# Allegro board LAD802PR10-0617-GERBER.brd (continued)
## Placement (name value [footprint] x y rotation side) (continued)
PC677  1U_0402_10V6K  [C_0402]  155.42 94.92 0 bottom
PC678  680P_0603_50V7K  [C_0603]  144.86 91.65 270 top
PC679  1000P_0402_50V7K  [C_0402]  152.05 88.44 180 top
PC680  1000P_0402_50V7K  [C_0402]  159.24 76.1 180 top
PC681  1000P_0402_50V7K  [C_0402]  148.94 98.16 180 bottom
PC685  1U_0402_10V6K  [C_0402]  149.45 73.74 180 top
PC686  10P_0402_25V8J  [C_0402]  159.24 75.18 180 bottom
PC687  10P_0402_25V8J  [C_0402]  148.94 97.27 180 top
PC688  10P_0402_25V8J  [C_0402]  152.05 87.55 180 top
PC690  33U_25V_M  [C_25CL33LD]  160.8 93.85 270 bottom
PC691  1000P_0402_25V8J  [C_0402]  159.24 75.18 180 top
PC692  1000P_0402_25V8J  [C_0402]  148.92 96.4 180 top
PC693  1000P_0402_25V8J  [C_0402]  148.94 96.39 180 bottom
PC694  1000P_0402_25V8J  [C_0402]  159.24 74.29 180 top
PC695  10P_0402_25V8J  [C_0402]  164.49 51.57 90 bottom
PC705  2200P_0402_25V7K  [C_0402]  198.96 30.11 90 bottom
PC708  0.1U_0402_25V6  [C_0402]  194.38 40.16 0 bottom
PC711  0.01UF_0402_25V7K  [C_0402]  189.81 33.1 0 top
PC721  0.22U_0402_16V7K  [C_0402]  199.74 35.33 180 bottom
PC742  5600P_0402_25V7K  [C_0402]  89.95 123.08 180 bottom
PC744  0.1U_0402_25V6  [C_0402]  95.13 123.08 0 bottom
PC747  0.1U_0402_25V6  [C_0402]  193.58 32.15 180 bottom
PC748  0.1U_0402_25V7K  [C_0402]  188.94 37.93 180 bottom
PC749  2200P_0402_25V7K  [C_0402]  188.03 39.33 0 bottom
PC750  0.22U_0603_25V7K  [C_0603]  194.71 30.69 90 bottom
PC751  560P_0402_50V7K  [C_0402]  190.44 41.39 270 bottom
PC752  0.015U_0402_25V7K  [C_0402]  190.43 42.31 0 bottom
PC753  10P_0402_50V8J  [C_0402]  192.6 41.93 0 bottom
PC757  1U_0603_25V6  [C_0603]  199.55 38.93 180 bottom
PC760  10U_0805_25V6K  [C_0805]  200.25 30.02 90 bottom
PC761  10U_0805_25V6K  [C_0805]  215.58 23.84 0 bottom
PC762  10U_0805_25V6K  [C_0805]  200.25 30.02 90 top
PC763  10U_0805_25V6K  [C_0805]  201.96 30.02 90 top
PC764  10U_0805_25V6K  [C_0805]  201.96 30.02 90 bottom
PC765  0.1U_0402_25V7K  [C_0402]  198.08 30.11 90 bottom
PC766  10U_0805_25V6K  [C_0805]  215.59 22.12 0 bottom
PC767  680P_0603_50V7K  [C_0603]  210.48 33.62 270 top
PC768  1U_0402_16V6K  [C_0402]  199.93 37.87 180 bottom
PC769  1U_0402_16V6K  [C_0402]  199.93 36.98 180 bottom
PC775  10U_0805_25V6K  [C_0805]  214.14 21.77 270 bottom
PC776  10U_0805_25V6K  [C_0805]  215.58 22.12 0 top
PC777  0.1U_0402_25V7K  [C_0402]  215.72 25.17 0 bottom
PC778  10U_0805_25V6K  [C_0805]  215.58 23.83 0 top
PC779  0.1U_0402_25V7K  [C_0402]  210.01 25.69 270 top
PC780  1000P_0402_25V8J  [C_0402]  198.96 30.11 90 top
PC781  1000P_0402_25V8J  [C_0402]  198.08 30.11 90 top
PC790  0.01U_0402_16V7K  [C_0402]  186.26 37.25 270 top
PC801  1U_0402_6.3V6K  [C_0402]  52.43 3.91 0 bottom
PC802  10U_0805_10V6K  [C_0805]  54.73 6.05 270 bottom
PC803  0.01U_0402_25V7K  [C_0402]  44.64 7.44 90 bottom
PC804  10U_0805_10V6K  [C_0805]  45.22 6.24 270 bottom
PC805  0.1U_0402_10V6K  [C_0402]  54.31 9.32 0 bottom
PC1001  22U_0603_6.3V6M  [C_0603]  116.56 51.72 90 top
PC1002  22U_0603_6.3V6M  [C_0603]  134.85 69.58 0 bottom
PC1003  22U_0603_6.3V6M  [C_0603]  143.53 75.14 270 bottom
PC1004  22U_0603_6.3V6M  [C_0603]  134.86 68.05 0 top
PC1005  22U_0603_6.3V6M  [C_0603]  115.35 51.72 90 top
PC1006  22U_0603_6.3V6M  [C_0603]  144.93 75.14 270 bottom
PC1007  22U_0603_6.3V6M  [C_0603]  111.73 51.7 90 top
PC1008  22U_0603_6.3V6M  [C_0603]  114.14 51.72 90 top
PC1009  22U_0603_6.3V6M  [C_0603]  112.94 51.7 90 top
PC1010  22U_0603_6.3V6M  [C_0603]  116.56 55.5 270 top
PC1011  22U_0603_6.3V6M  [C_0603]  115.35 55.49 270 top
PC1012  22U_0603_6.3V6M  [C_0603]  134.86 65 0 top
PC1013  22U_0603_6.3V6M  [C_0603]  138.07 67.02 0 bottom
PC1014  22U_0603_6.3V6M  [C_0603]  115.34 91.01 270 bottom
PC1015  22U_0603_6.3V6M  [C_0603]  113.81 91.01 270 bottom
PC1016  22U_0603_6.3V6M  [C_0603]  112.29 87.72 270 bottom
PC1017  22U_0603_6.3V6M  [C_0603]  116.98 84.67 270 bottom
PC1018  22U_0603_6.3V6M  [C_0603]  110.78 87.78 270 bottom
PC1019  22U_0603_6.3V6M  [C_0603]  115.33 87.7 270 bottom
PC1020  22U_0603_6.3V6M  [C_0603]  116.93 87.73 270 bottom
PC1021  22U_0603_6.3V6M  [C_0603]  115.37 84.72 270 bottom
PC1022  22U_0603_6.3V6M  [C_0603]  113.85 84.7 270 bottom
PC1023  22U_0603_6.3V6M  [C_0603]  116.92 94 270 bottom
PC1024  22U_0603_6.3V6M  [C_0603]  113.69 94 270 bottom
PC1025  22U_0603_6.3V6M  [C_0603]  116.92 96.92 270 bottom
PC1026  22U_0603_6.3V6M  [C_0603]  112.03 96.98 270 bottom
PC1027  22U_0603_6.3V6M  [C_0603]  115.34 94 270 bottom
PC1028  22U_0603_6.3V6M  [C_0603]  114.64 66.3 270 top
PC1029  22U_0603_6.3V6M  [C_0603]  115.84 66.3 270 top
PC1030  1U_0201_6.3V6M  [C_0201]  108.02 53.63 270 top
PC1031  1U_0201_6.3V6M  [C_0201]  110.21 58.92 90 top
PC1032  1U_0201_6.3V6M  [C_0201]  110.8 53.18 90 top
PC1033  1U_0201_6.3V6M  [C_0201]  109.06 58.92 90 top
PC1034  1U_0201_6.3V6M  [C_0201]  109.67 55.41 270 top
PC1035  1U_0201_6.3V6M  [C_0201]  110.78 58.92 90 top
PC1036  1U_0201_6.3V6M  [C_0201]  109.67 53.18 90 top
PC1037  1U_0201_6.3V6M  [C_0201]  110.24 53.18 90 top
PC1038  1U_0201_6.3V6M  [C_0201]  108.1 54.38 90 top
PC1039  1U_0201_6.3V6M  [C_0201]  110.23 55.41 270 top
PC1040  1U_0201_6.3V6M  [C_0201]  111.15 66.46 270 top
PC1041  1U_0201_6.3V6M  [C_0201]  110 66.46 270 top
PC1042  1U_0201_6.3V6M  [C_0201]  108.31 63.18 0 top
PC1043  1U_0201_6.3V6M  [C_0201]  110.64 61.23 270 top
PC1044  1U_0201_6.3V6M  [C_0201]  111.27 61.23 270 top
PC1045  1U_0201_6.3V6M  [C_0201]  109.37 61.23 270 top
PC1046  1U_0201_6.3V6M  [C_0201]  110.03 65.28 0 top
PC1047  1U_0201_6.3V6M  [C_0201]  110 61.23 270 top
PC1048  1U_0201_6.3V6M  [C_0201]  117.34 59.37 180 top
PC1049  1U_0201_6.3V6M  [C_0201]  108.73 61.23 270 top
PC1050  1U_0201_6.3V6M  [C_0201]  110.8 55.4 270 top
PC1051  1U_0201_6.3V6M  [C_0201]  111.46 59.26 0 top
PC1052  1U_0201_6.3V6M  [C_0201]  111.46 58.69 0 top
PC1053  1U_0201_6.3V6M  [C_0201]  110.78 56.62 90 top
PC1054  1U_0201_6.3V6M  [C_0201]  110.22 56.62 90 top
PC1055  1U_0201_6.3V6M  [C_0201]  117.34 58.8 180 top
PC1056  1U_0201_6.3V6M  [C_0201]  110.03 64.71 0 top
PC1057  22U_0603_6.3V6M  [C_0603]  117.24 48.2 90 top
PC1058  22U_0603_6.3V6M  [C_0603]  151.92 56.15 270 top
PC1059  22U_0603_6.3V6M  [C_0603]  150.08 56.15 270 top
PC1060  22U_0603_6.3V6M  [C_0603]  148.43 56.15 270 top
PC1061  22U_0603_6.3V6M  [C_0603]  116.53 56.53 90 top
PC1062  330U_2V_M  [C_5X4P5]  136.61 80.77 270 bottom
PC1063  330U_2V_M  [C_5X4P5]  135.28 93.36 90 bottom
PC1064  22U_0603_6.3V6M  [C_0603]  115.32 56.52 90 top
PC1065  22U_0603_6.3V6M  [C_0603]  114.12 56.52 90 top
PC1066  22U_0603_6.3V6M  [C_0603]  112.91 56.52 90 top
PC1067  22U_0603_6.3V6M  [C_0603]  111.7 56.52 90 top
PC1068  22U_0603_6.3V6M  [C_0603]  134.85 68.05 0 bottom
PC1069  22U_0603_6.3V6M  [C_0603]  138.04 71.63 0 top
PC1070  22U_0603_6.3V6M  [C_0603]  136.42 75.14 270 bottom
PC1071  22U_0603_6.3V6M  [C_0603]  134.86 66.53 0 top
PC1072  22U_0603_6.3V6M  [C_0603]  138.07 67.02 0 top
PC1073  22U_0603_6.3V6M  [C_0603]  138.06 68.54 0 bottom
PC1074  22U_0603_6.3V6M  [C_0603]  140.61 75.14 270 bottom
PC1075  22U_0603_6.3V6M  [C_0603]  139.21 75.14 270 bottom
PC1076  22U_0603_6.3V6M  [C_0603]  134.85 66.53 0 bottom
PC1077  22U_0603_6.3V6M  [C_0603]  134.85 65 0 bottom
PC1078  22U_0603_6.3V6M  [C_0603]  138.07 70.06 0 top
PC1079  22U_0603_6.3V6M  [C_0603]  137.82 75.14 270 bottom
PC1080  22U_0603_6.3V6M  [C_0603]  138.07 70.07 0 bottom
PC1081  22U_0603_6.3V6M  [C_0603]  138.07 68.53 0 top
PC1082  22U_0603_6.3V6M  [C_0603]  135.02 75.14 270 bottom
PC1083  1U_0201_6.3V6M  [C_0201]  109.62 56.61 90 top
PC1084  1U_0201_6.3V6M  [C_0201]  109.05 56.61 90 top
PC1085  1U_0201_6.3V6M  [C_0201]  107.45 53.65 270 top
PC1086  1U_0201_6.3V6M  [C_0201]  110.26 52.11 270 top
PC1087  1U_0201_6.3V6M  [C_0201]  110.83 52.11 270 top
PC1088  1U_0201_6.3V6M  [C_0201]  109.63 58.92 90 top
PC1089  1U_0201_6.3V6M  [C_0201]  117.27 50.92 180 top
PC1090  1U_0201_6.3V6M  [C_0201]  117.27 50.36 180 top
PC1091  1U_0201_6.3V6M  [C_0201]  112.17 50.36 0 top
PC1092  1U_0201_6.3V6M  [C_0201]  114.42 50.93 180 top
PC1093  1U_0201_6.3V6M  [C_0201]  115.03 50.36 0 top
PC1094  1U_0201_6.3V6M  [C_0201]  115.03 50.93 0 top
PC1095  1U_0201_6.3V6M  [C_0201]  114.42 50.36 180 top
PC1096  1U_0201_6.3V6M  [C_0201]  112.17 50.93 0 top
PC1097  1U_0201_6.3V6M  [C_0201]  111.55 50.93 180 top
PC1098  1U_0201_6.3V6M  [C_0201]  111.56 50.36 180 top
PC1099  1U_0201_6.3V6M  [C_0201]  109.33 50.93 0 top
PC1101  330U_2V_M  [C_5X4P5]  125.88 102.85 270 bottom
PC1125  1U_0201_6.3V6M  [C_0201]  109.33 50.36 0 top
PC1126  1U_0201_6.3V6M  [C_0201]  109.68 52.11 270 top
PC1127  330U_2V_M  [C_5X4P5]  142.64 80.82 270 bottom
PC1128  330U_2V_M  [C_5X4P5]  132.1 102.85 270 bottom
PC1129  22U_0603_6.3V6M  [C_0603]  117.05 63.88 270 top
PC1130  22U_0603_6.3V6M  [C_0603]  112.25 84.71 270 bottom
PC1131  22U_0603_6.3V6M  [C_0603]  112.22 66.3 270 top
PC1132  22U_0603_6.3V6M  [C_0603]  110.74 84.72 270 bottom
PC1133  22U_0603_6.3V6M  [C_0603]  115.84 63.88 270 top
PC1134  22U_0603_6.3V6M  [C_0603]  110.7 91.01 270 bottom
PC1135  22U_0603_6.3V6M  [C_0603]  110.51 94 270 bottom
PC1136  22U_0603_6.3V6M  [C_0603]  110.76 81.73 270 bottom
PC1137  22U_0603_6.3V6M  [C_0603]  117.05 66.3 270 top
PC1138  22U_0603_6.3V6M  [C_0603]  113.43 66.3 270 top
PC1139  22U_0603_6.3V6M  [C_0603]  148.43 56.15 270 bottom
PC1140  22U_0603_6.3V6M  [C_0603]  151.92 56.15 270 bottom
PC1141  22U_0603_6.3V6M  [C_0603]  150.08 56.15 270 bottom
PC1142  22U_0603_6.3V6M  [C_0603]  114.83 48.2 90 top
PC1143  22U_0603_6.3V6M  [C_0603]  113.62 48.2 90 top
PC1144  22U_0603_6.3V6M  [C_0603]  112.42 48.2 90 top
PC1145  22U_0603_6.3V6M  [C_0603]  111.21 48.2 90 top
PC1146  22U_0603_6.3V6M  [C_0603]  116.03 48.2 90 top
PC1147  1U_0201_6.3V6M  [C_0201]  109.75 48.87 90 top
PC1148  1U_0201_6.3V6M  [C_0201]  109.19 48.87 90 top
PC1149  1U_0201_6.3V6M  [C_0201]  110.79 47.44 0 top
PC1150  1U_0201_6.3V6M  [C_0201]  110 47.73 270 top
PC1151  1U_0201_6.3V6M  [C_0201]  109.43 48.24 270 top
PC1152  1U_0201_6.3V6M  [C_0201]  113.82 47.36 180 top
PC1153  1U_0201_6.3V6M  [C_0201]  110.31 48.87 90 top
PC1154  22U_0603_6.3V6M  [C_0603]  113.87 81.73 270 bottom
PC1155  22U_0603_6.3V6M  [C_0603]  112.29 81.73 270 bottom
PC1156  22U_0603_6.3V6M  [C_0603]  115.34 96.92 270 bottom
PC1158  22U_0603_6.3V6M  [C_0603]  114.64 63.88 270 top
PC1159  22U_0603_6.3V6M  [C_0603]  113.43 63.88 270 top
PC1161  22U_0603_6.3V6M  [C_0603]  111.02 63.88 270 top
PC1162  22U_0603_6.3V6M  [C_0603]  109.81 63.88 270 top
PC1163  22U_0603_6.3V6M  [C_0603]  112.22 63.88 270 top
PC1164  1U_0201_6.3V6M  [C_0201]  107.5 55.51 180 top
PC1170  22U_0603_6.3V6M  [C_0603]  114.14 55.49 270 top
PC1171  22U_0603_6.3V6M  [C_0603]  111.73 55.49 270 top
PC1172  22U_0603_6.3V6M  [C_0603]  112.94 55.49 270 top
PC1173  22U_0603_6.3V6M  [C_0603]  142.07 75.14 270 bottom
PC1174  22U_0603_6.3V6M  [C_0603]  134.86 69.58 0 top
PC1175  22U_0603_6.3V6M  [C_0603]  113.43 61.53 270 top
PC1176  22U_0603_6.3V6M  [C_0603]  117.05 61.53 270 top
PC1177  22U_0603_6.3V6M  [C_0603]  115.84 61.53 270 top
PC1178  22U_0603_6.3V6M  [C_0603]  117.02 81.71 270 bottom
PC1179  22U_0603_6.3V6M  [C_0603]  113.69 96.92 270 bottom
PC1180  22U_0603_6.3V6M  [C_0603]  114.32 78.5 90 top
PC1181  22U_0603_6.3V6M  [C_0603]  114.64 61.53 270 top
PC1182  22U_0603_6.3V6M  [C_0603]  115.59 78.5 90 top
PC1183  22U_0603_6.3V6M  [C_0603]  112.22 61.53 270 top
PC1184  22U_0603_6.3V6M  [C_0603]  116.99 91.01 270 bottom
PC1201  0.1U_0402_10V7K  [C_0402]  95.21 109 0 bottom
PC1202  0.1U_0402_25V6  [C_0402]  99.39 115.54 0 top
PC1203  10U_0603_25V6M  [C_0603]  99.36 114.43 0 bottom
PC1204  0.1U_0402_25V6  [C_0402]  102.97 113.32 0 bottom
PC1205  1U_0402_6.3V6K  [C_0402]  96.69 111.54 180 bottom
PC1206  22U_0603_6.3V6M  [C_0603]  102.85 100.47 90 bottom
PC1207  22U_0603_6.3V6M  [C_0603]  97.16 100.66 180 bottom
PC1208  22U_0603_6.3V6M  [C_0603]  97.21 101.95 180 bottom
PC1209  680P_0402_50V7K  [C_0402]  96.49 103.82 180 bottom
PC1210  2200P_0402_50V7K  [C_0402]  99.39 116.5 0 bottom
PC1211  0.1U_0402_25V6  [C_0402]  99.39 116.5 0 top
PC1212  2200P_0402_50V7K  [C_0402]  99.39 115.54 0 bottom
PC1221  22U_0603_6.3V6M  [C_0603]  115.44 81.72 270 bottom
PC1222  22U_0603_6.3V6M  [C_0603]  112.1 93.93 270 bottom
PC1223  22U_0603_6.3V6M  [C_0603]  113.83 87.72 270 bottom
PC1224  22U_0603_6.3V6M  [C_0603]  112.22 91.01 270 bottom
PD2  -  [TVNST52302AB0_SOT523-3]  215.02 12.65 180 top
PD3  -  [TVNST52302AB0_SOT523-3]  217.18 12.66 180 top
PD4  -  [TVNST52302AB0_SOT523-3]  64.53 111.65 90 top
PD5  -  [BAV99W_SC70-3]  73.78 116.99 270 top
PD6  -  [BAV99W_SC70-3]  71.46 113.33 180 top
PD102  -  [SDMK0340L-7-F_SOD323-2]  179.6 29.04 0 top
PD704  -  [LRB715FT1G_SOT323-3]  202.14 39.65 0 bottom
PH601  470K_0402_5%_ TSM0B474J4702RE  [R_0402]  150.71 96.4 180 bottom
PH602  10K_0402_5%_ERTJ0ER103J  [R_0402]  140.05 88.47 0 bottom
PH603  470K_0402_5%_ TSM0B474J4702RE  [R_0402]  157.04 84.62 0 bottom
PH604  10KB_0402_5%_ERTJ0ER103J  [R_0402]  153.51 58.31 90 bottom
PH605  10KB_0402_5%_ERTJ0ER103J  [R_0402]  148.37 77.11 180 bottom
PJP1  JUMP_43X79  [JUMP_43X79-NPM]  81.69 120.62 180 bottom
PJP2  JUMP_43X79  [JUMP_43X79-NPM]  71.55 119.9 90 bottom
PJP3  JUMP_43X79  [JUMP_43X79-NPM]  202.94 18.83 90 bottom
PJP102  -  [JUMP_43X118]  160.78 41.11 180 top
PJP103  -  [JUMP_43X118]  173.37 24.13 270 top
PJP105  -  [JUMP_43X79]  175.78 49.71 270 bottom
PJP106  -  [JUMP_43X79]  180.71 39.39 270 bottom
PJP200  -  [JUMP_43X118]  65.51 103.33 270 top
PJP203  -  [JUMP_43X79]  84.73 114.23 270 top
PJP206  -  [JUMP_43X79]  78.57 110.57 90 bottom
PJP301  -  [JUMP_43X79]  157.34 45.72 180 bottom
PJP302  -  [JUMP_43X118]  138.74 42.76 180 bottom
PJP501  -  [JUMP_43X79]  156.93 38.86 270 bottom
PJP502  -  [JUMP_43X79]  166.13 27.43 270 bottom
PJP601  PAD-OPEN 4X4M  [JUMP_43X118-NPM]  163.14 76.46 0 bottom
PJP602  PAD-OPEN 4X4M  [JUMP_43X118]  156.2 99.74 90 bottom
PJP603  PAD-OPEN1X1M  [JUMP_43X39]  153.31 69.06 270 bottom
PJP701  -  [JUMP_43X118]  200.64 24.9 90 bottom
PJP801  -  [JUMP_43X79]  58.13 5.97 180 bottom
PJP802  -  [JUMP_43X79]  42.13 7.53 90 bottom
PJP1201  -  [JUMP_43X79]  96.12 115.64 0 bottom
PJP1202  -  [JUMP_43X79]  99.98 100.39 270 bottom
PJPDC1  ACES_50458-00601-001  [ACES_50458-00601-001_6P-T]  70.6 124.25 0 bottom
PL1  HCB3225KF-151T50_2P  [5A_Z150_1210_2P]  79.82 120.63 0 bottom
PL2  BLM15AG102SN1D_2P  [MURAT_BLM15AG102SN1D_2P]  74.87 121.94 180 bottom
PL3  HCB3225KF-151T50_2P  [5A_Z150_1210_2P]  202.91 20.76 270 bottom
PL4  HCB3225KF-151T50_2P  [5A_Z150_1210_2P]  71.57 121.83 270 bottom
PL100  1.5UH_9A_20%_7X7X3_M  [L_7X7X3_M_2P]  171.09 42.63 180 bottom
PL101  2.2UH_7.8A_20%_7X7X3_M  [L_7X7X3_M_2P]  171.85 34.29 270 bottom
PL102  HCB3225KF-151T50_2P  [5A_Z150_1210_2P-NPM]  175.8 50.43 270 bottom
PL103  HCB3225KF-151T50_2P  [5A_Z150_1210_2P-NPM]  180.73 40.2 270 bottom
PL200  1UH_11A_20%_7X7X3_M  [L_7X7X3_M_2P]  69.28 104.85 0 bottom
PL201  HCB3225KF-151T50_2P  [5A_Z150_1210_2P-NPM]  78.55 112.55 270 bottom
PL301  1UH_6.6A_20%_5X5X3_M  [L_5X5X3_M_2P]  146.25 42.99 180 bottom
PL302  HCB3225KF-151T50_2P  [5A_Z150_1210_2P-NPM]  158.17 45.7 180 bottom
PL501  1UH_6.6A_20%_5X5X3_M  [L_5X5X3_M_2P]  165.12 34.77 270 bottom
PL601  0.68UH +-20% 7.9A  [L_5X5X3_M]  150 58.56 90 bottom
PL602  HCB3225KF-151T50_2P  [5A_Z150_1210_2P]  162.37 76.42 0 bottom
PL603  .15UH +-20% 29A 7X7X4 MOLDING  [L_7X7X4_M]  147.62 81.49 0 bottom
PL604  .15UH +-20% 29A 7X7X4 MOLDING  [L_7X7X4_M]  137.18 102.51 0 bottom
PL605  .15UH +-20% 29A 7X7X4 MOLDING  [L_7X7X4_M]  140.16 92.8 0 bottom
PL606  HCB3225KF-151T50_2P  [5A_Z150_1210_2P-NPM]  156.2 98.94 90 bottom
PL700  4.7UH_5.5A_20%_7X7X3_M  [L_7X7X3_M_2P]  209.12 32.15 0 bottom
PL704  1UH_PCMB053T-1R0MS_7A_20%  [L_5X5X3_M_2P-NPM]  200.67 23.28 90 bottom
PL1201  0.68UH_7.9A_20%_5X5X3_M  [L_5X5X3_M_2P]  100.01 107.84 270 bottom
PL1202  HCB3225KF-151T50_2P  [5A_Z150_1210_2P-NPM]  95.17 115.62 0 bottom
PQ1  L2N7002DW1T1G_SC88-6  [2N7002DW-T-R7_SOT363-6]  185.12 22.24 90 top
PQ2  L2N7002DW1T1G_SC88-6  [2N7002DW-T-R7_SOT363-6]  179.17 23.57 270 top
PQ3  -  [L2N7002WT1G_SC70-3]  180.81 25.65 90 top
PQ5  MMST3904-7-F_SOT323  [RHU002N06_SOT323-3]  72.22 111.23 270 top
PQ6  FDV301N_G 1N SOT23-3  [FDV301N_NL_SOT23-3]  66.73 113.68 270 top
PQ201  -  [AON7934_DFN3X3A8-10]  78.1 106.24 0 bottom
PQ601  AON7934_DFN3X3A-8-10  [AON7934_DFN3X3A8-10]  151.32 67.63 270 bottom
PQ704  AON7408L_DFN8-5  [SIS412DN-T1-GE3_POWERPAK8-5]  206.45 31.28 270 bottom
PQ708  AON7506_DFN33-8-5  [SIS412DN-T1-GE3_POWERPAK8-5]  203.56 33.26 90 bottom
PQ709  -  [L2N7002WT1G_SC70-3]  91.69 122.32 90 bottom
PQ710  -  [LMUN5113T1G_SOT323-3]  202.27 23.58 180 top
PQ711  -  [LTC015EUBFS8TL_UMT3F]  200.4 21.68 270 top
PQ712  -  [L2N7002WT1G_SC70-3]  91.67 119.74 270 bottom
PQ717  -  [MDU1512RH_POWERDFN56-8-5]  210.04 27.2 270 bottom
PQ718  -  [MDU1512RH_POWERDFN56-8-5]  95.93 126.29 90 bottom
PQ720  -  [RUM002N02GT2L_VMT3]  186.77 39.9 90 top
PQ721  -  [RUM002N02GT2L_VMT3]  188.3 36.79 270 top
PQ740  -  [MDU1512RH_POWERDFN56-8-5]  93.54 128.54 270 bottom
PR2  1M_0402_1%  [R_0402]  185.19 21.1 180 top
PR3  2.2K_0402_5%  [R_0402]  70.06 117.1 90 top
PR4  33_0402_5%  [R_0402]  69.11 116.15 90 top
PR5  3.3K_1206_5%  [R_1206]  184.17 25.35 0 top
PR6  100K_0402_1%  [R_0402]  67.79 111.21 180 top
PR7  1M_0402_1%  [R_0402]  182.92 24.92 90 top
PR8  10K_0402_1%  [R_0402]  70.96 116.16 180 top
PR9  15K_0402_1%  [R_0402]  74.07 113.87 180 top
PR10  1M_0402_1%  [R_0402]  183.34 21.1 180 top
PR11  100K_0402_1%  [R_0402]  70.57 112.08 90 top
PR12  0_0402_5%  [R_0402]  187.41 23.64 180 top
PR13  0_0402_5%  [R_0402]  187.4 22.71 180 top
PR15  200_0402_5%  [R_0402]  216.72 16 270 top
PR16  10K_0402_1%  [R_0402]  217.66 15.07 90 top
PR18  100_0402_5%  [R_0402]  214.52 16 270 top
PR20  100_0402_5%  [R_0402]  215.52 16 270 top
PR28  10K_0402_1%  [R_0402]  179.59 21.12 180 top
PR29  100K_0402_1%  [R_0402]  177.59 23.33 90 top
PR31  1M_0402_1%  [R_0402]  181.97 24.92 90 top
PR32  100K_0402_1%  [R_0402]  177.61 26.55 270 top
PR33  1M_0402_1%  [R_0402]  180.49 21.1 0 top
PR100  0_0603_5%  [R0603_0OHM]  173.44 45.58 90 bottom
PR102  499K_0402_1%  [R_0402]  179.01 41.43 0 bottom
PR103  499K_0402_1%  [R_0402]  179.01 42.31 0 bottom
PR106  4.7_1206_5%  [R_1206]  169.25 44.6 180 top
PR107  10K_0402_1%  [R_0402]  173.49 37.81 0 bottom
PR108  1K_0402_5%  [R_0402]  174.4 38.7 180 bottom
PR109  150K_0402_1%  [R_0402]  173.49 39.58 0 bottom
PR110  150K_0402_1%  [R_0402]  176.17 39.6 270 bottom
PR111  0_0603_5%  [R0603_0OHM]  177.25 35.77 180 bottom
PR112  4.7_1206_5%  [R_1206]  172.68 34.95 270 top
PR113  10K_0402_1%  [R_0402]  182.01 30.49 180 bottom
PR114  2.2K_0402_5%  [R_0402]  182.66 28.47 180 bottom
PR115  150K_0402_1%  [R_0402]  177.3 29.36 0 bottom
PR116  0_0402_5%  [R0402_0OHM]  178.07 28.46 90 top
PR117  1K_0402_5%  [R_0402]  178.21 28.47 180 bottom
PR118  150K_0402_1%  [R_0402]  179.98 29.37 270 bottom
PR120  0_0402_5%  [R0402_0OHM]  180.87 29.37 270 bottom
PR121  0_0402_5%  [R0402_0OHM]  177.06 39.6 270 bottom
PR122  1M_0402_5%  [R_0402]  177.06 37.81 270 bottom
PR200  0_0603_5%  [R0603_0OHM]  83.59 105.62 90 bottom
PR201  0_0402_5%  [R0402_0OHM]  91.79 106.25 180 bottom
PR202  0_0402_5%  [R0402_0OHM]  91.79 108.92 180 bottom
PR203  4.7_1206_5%  [R_1206]  73.8 104.18 90 top
PR204  100K_0402_1%  [R_0402]  90.88 109.94 0 bottom
PR205  11K_0402_1%  [R_0402]  86.62 102.24 90 bottom
PR206  5.1_0603_5%  [R_0603]  90.61 101.75 90 bottom
PR207  60.4K_0402_1%  [R_0402]  90.04 110.81 180 bottom
PR208  453K_0402_1%  [R_0402]  91.79 105.36 180 bottom
PR209  10K_0402_1%  [R_0402]  91.79 104.48 180 bottom
PR210  2.2_0603_5%  [R_0603]  89.36 103.14 270 bottom
PR301  0_0402_5%  [R0402_0OHM]  154.39 38.62 90 bottom
PR302  1M_0402_1%  [R_0402]  153.5 40.4 90 bottom
PR303  0_0402_5%  [R0402_0OHM]  148.16 38.62 90 bottom
PR304  0_0402_5%  [R0402_0OHM]  153.5 38.62 90 bottom
PR305  0_0402_5%  [R_0402]  152.61 39.53 270 bottom
PR306  0_0603_5%  [R0603_0OHM]  148.8 45.74 90 bottom
PR307  4.7_1206_5%  [R_1206]  146.31 47.07 180 bottom
PR308  10_0402_5%  [R_0402]  149.05 39.53 270 bottom
PR309  21.5K_0402_1%  [R_0402]  150.84 39.52 180 bottom
PR310  31.6K_0402_1%  [R_0402]  151.72 39.53 270 bottom
PR501  0_0402_5%  [R0402_0OHM]  160.79 31.01 0 bottom
PR502  1M_0402_5%  [R_0402]  160.79 31.9 0 bottom
PR503  10_0402_5%  [R_0402]  159.01 31.9 0 bottom
PR504  20K_0402_1%  [R_0402]  158.13 32.8 270 bottom
PR505  10K_0402_1%  [R_0402]  157.93 31.01 0 bottom
PR506  4.7_1206_5%  [R_1206]  164.55 35.27 270 top
PR601  45.3_0402_1%  [R_0402]  165.37 54.71 270 bottom
PR602  0_0402_5%  [R0402_0OHM]  161.45 56.09 180 bottom
PR603  0_0402_5%  [R0402_0OHM]  161.83 54.7 180 top
PR604  75_0402_1%  [R_0402]  164.48 54.71 270 bottom
PR605  100_0402_1%  [R_0402]  163.59 54.71 270 bottom
PR606  0_0402_5%  [R0402_0OHM]  167.16 53.81 180 bottom
PR607  0_0402_5%  [R0402_0OHM]  160.48 54.71 270 bottom
PR608  78.7K_0402_1%  [R_0402]  159.42 54.19 180 top
PR609  0_0402_5%  [R0402_0OHM]  162.71 54.71 270 bottom
PR610  10K_0402_1%  [R_0402]  168.1 57.27 90 top
PR611  48.7K_0402_1%  [R_0402]  159.42 55.08 180 top
PR612  1.91K_0402_1%  [R_0402]  166.26 53.8 90 top
PR613  86.6K_0402_1%  [R_0402]  165.36 56.72 0 bottom
PR615  0_0402_5%  [R_0402]  168.97 62.99 180 bottom
PR616  0_0402_5%  [R0402_0OHM]  167.15 53.8 90 top
PR617  3.6K_0402_1%  [R_0402]  168.11 56.64 90 bottom
PR618  49.9_0402_1%  [R_0402]  164.48 53.8 90 top
PR619  0_0603_5%  [R_0603]  150.58 74.06 180 bottom
PR620  0_0402_5%  [R0402_0OHM]  168.98 55.49 180 top
PR621  1K_0402_1%  [R_0402]  169.89 59.08 180 top
PR622  1.96K_0402_1%  [R_0402]  168.1 59.96 270 top
PR623  2K_0402_1%  [R_0402]  169.89 58.17 180 top
PR624  3.65K_0603_1%  [R_0603]  154.13 55.46 90 top
PR625  0_0402_5%  [R0402_0OHM]  163.59 53.8 90 top
PR626  10_0402_1%  [R_0402]  162.71 53.8 90 top
PR627  4.7_1206_5%  [R_1206]  150.06 64.15 180 top
PR628  4.42K_0402_1%  [R_0402]  170.71 60.27 90 bottom
PR629  84.5K_0402_1%  [R_0402]  165.24 61.12 90 bottom
PR630  4.02K_0402_1%  [R_0402]  160.55 57.89 270 bottom
PR631  27.4K_0402_1%  [R_0402]  169 56.4 180 top
PR632  1K_0402_1%  [R_0402]  169.82 62.08 270 top
PR633  11K_0402_1%  [R_0402]  169.82 60.27 90 bottom
PR634  0_0402_5%  [R_0402]  168.97 63.87 180 bottom
PR635  10K_0402_1%  [R_0402]  164.61 64.3 270 top
PR636  1.24K_0402_1%  [R_0402]  158.78 56.86 180 top
PR637  20M_0402_5%  [R_0402]  166.28 59.71 180 bottom
PR638  274_0402_1%  [R_0402]  168.94 62.06 180 top
PR639  3K_0402_1%  [R_0402]  162.58 61.12 90 bottom
PR640  255_0402_1%  [R_0402]  157.96 62.57 180 top
PR641  1K_0402_1%  [R_0402]  156.99 55.95 90 top
PR642  2.61K_0402_1%  [R_0402]  155.21 56.87 270 top
PR643  11K_0402_1%  [R_0402]  157.88 57.73 90 top
PR644  1K_0402_1%  [R_0402]  157.96 63.46 180 top
PR645  316_0402_1%  [R_0402]  163.34 65.12 270 top
PR646  316_0402_1%  [R_0402]  158.84 60.78 180 top
PR647  27.4K_0402_1%  [R_0402]  165.51 65.17 180 top
PR648  1.37K_0402_1%  [R_0402]  162.44 63.33 0 top
PR649  1.69K_0402_1%  [R_0402]  158.84 59.9 180 top
PR650  2K_0402_1%  [R_0402]  164.6 66.06 0 top
PR651  140K_0402_1%  [R_0402]  160.54 60.53 0 bottom
PR652  2K_0402_1%  [R_0402]  158.84 61.67 180 top
PR653  20M_0402_5%  [R_0402]  160.1 62.94 90 bottom
PR654  20M_0402_5%  [R_0402]  156.1 58.65 270 top
PR655  0_0402_5%  [R0402_0OHM]  153.76 96.23 180 bottom
PR656  11K_0402_1%  [R_0402]  158.34 61.68 180 bottom
PR657  4.42K_0402_1%  [R_0402]  159.21 62.94 90 bottom
PR659  0_0402_5%  [R0402_0OHM]  162.74 83.26 0 bottom
PR660  0_0603_5%  [R_0603]  163.96 81.18 180 bottom
PR661  3.65K_0603_1%  [R_0603]  156.29 64.54 0 bottom
PR662  5.11K_0402_1%  [R_0402]  161.36 84.85 0 bottom
PR663  4.7_1206_5%  [R_1206]  154.58 81.3 180 top
PR664  0_0402_5%  [R_0402]  152.15 104.86 0 bottom
PR665  0_0603_5%  [R_0603]  153.64 102.88 180 bottom
PR666  10_0402_1%  [R_0402]  168.17 64.8 270 top
PR667  3.65K_0603_1%  [R_0603]  170.94 59.14 0 bottom
PR668  100K_0402_1%  [R_0402]  168.99 65.68 180 bottom
PR669  4.7_1206_5%  [R_1206]  143.43 104.41 270 top
PR670  100K_0402_1%  [R_0402]  168.99 64.79 180 bottom
PR671  0_0402_5%  [R0402_0OHM]  155.29 95.81 0 bottom
PR672  0_0603_5%  [R_0603]  156.53 92.91 180 bottom
PR673  10_0402_1%  [R_0402]  169.82 62.97 270 bottom
PR674  3.65K_0603_1%  [R_0603]  170.94 57.82 0 bottom
PR675  100K_0402_1%  [R_0402]  166.2 63.9 270 bottom
PR676  4.7_1206_5%  [R_1206]  146.51 94.26 270 top
PR677  100K_0402_1%  [R_0402]  167.15 62.74 90 bottom
PR678  100_0402_1%  [R_0402]  165.37 53.8 90 top
PR679  0_0402_5%  [R0402_0OHM]  148.17 72.14 90 bottom
PR680  5.11K_0402_1%  [R_0402]  166.39 63.38 90 top
PR681  5.11K_0402_1%  [R_0402]  165.51 63.35 90 top
PR703  0.01_1206_1%  [R_1206_4P]  99.19 124.07 0 bottom
PR727  10.5K_0402_1%  [R_0402]  190.72 39.33 180 bottom
PR729  392K_0402_1%  [R_0402]  189.81 32.21 0 top
PR731  158K_0402_1%  [R_0402]  190.72 33.11 180 bottom
PR732  53.6K_0402_1%  [R_0402]  190.72 32.22 180 bottom
PR737  3M_0402_5%  [R_0402]  95.14 122.01 270 bottom
PR738  1M_0402_1%  [R_0402]  96.2 121.07 90 bottom
PR740  2_0402_5%  [R_0402]  193.63 30.36 90 bottom
PR741  100K_0402_1%  [R_0402]  189.81 34 0 bottom
PR742  2_0402_5%  [R_0402]  195.28 41.03 90 bottom
PR743  10_1206_5%  [R_1206]  198.2 40.54 0 bottom
PR745  100_0402_1%  [R_0402]  196.17 32.17 270 bottom
PR749  200K_0402_1%  [R_0402]  193.5 40.14 90 top
PR750  200K_0402_1%  [R_0402]  192.61 40.14 90 top
PR751  75K_0402_1%  [R_0402]  196.17 40.17 270 bottom
PR752  66.5K_0402_1%  [R_0402]  191.73 41.06 270 top
PR753  182K_0402_1%  [R_0402]  189.5 41.72 270 bottom
PR754  100_0402_1%  [R_0402]  191.33 41.39 270 bottom
PR755  102K_0402_1%  [R_0402]  192.61 41.06 270 bottom
PR756  10K_0402_1%  [R_0402]  193.52 42.82 180 bottom
PR757  100K_0402_1%  [R_0402]  197.06 40.17 270 bottom
PR760  4.7_0402_5%  [R_0402]  198.14 37.88 270 bottom
PR761  0_0603_5%  [R0603_0OHM]  198.08 34.25 0 bottom
PR762  4.02K_0402_1%  [R_0402]  95.13 123.97 0 bottom
PR763  4.02K_0402_1%  [R_0402]  98.17 124.69 270 bottom
PR764  10K_0402_1%  [R_0402]  193.5 41.06 270 bottom
PR765  0.01_1206_1%  [R_1206_4P]  213.7 27.9 270 bottom
PR766  4.7_1206_5%  [R_1206]  208.81 30.95 90 top
PR769  0_0402_5%  [R0402_0OHM]  189.81 34.89 0 bottom
PR770  0_0402_5%  [R0402_0OHM]  189.81 35.77 0 bottom
PR771  0_0603_5%  [R0603_0OHM]  198.08 32.98 0 bottom
PR772  0_0402_5%  [R0402_0OHM]  192.74 30.36 90 bottom
PR773  0_0603_5%  [R0603_0OHM]  208.62 23.71 0 top
PR774  1K_0402_1%  [R_0402]  189.81 37.55 0 bottom
PR775  0_0402_5%  [R0402_0OHM]  189.81 38.44 0 bottom
PR776  0_0402_5%  [R0402_0OHM]  194.39 41.03 90 bottom
PR777  0_0402_5%  [R_0402]  189.81 36.66 0 bottom
PR778  0_0402_5%  [R0402_0OHM]  92.82 130.78 0 bottom
PR779  0_0402_5%  [R0402_0OHM]  196.16 41.04 0 bottom
PR780  0_0603_5%  [R_0603]  204.11 22.95 270 top
PR781  10K_0402_5%  [R_0402]  190.67 39.12 180 top
PR790  160K_0402_1%  [R_0402]  186.26 39.03 270 top
PR791  10K_0402_5%  [R_0402]  186.26 41.69 270 top
PR801  21.5K_0402_1%  [R_0402]  45.61 7.47 90 bottom
PR802  10K_0402_1%  [R_0402]  44.64 9.47 0 bottom
PR803  0_0402_5%  [R0402_0OHM]  55.26 8.28 180 bottom
PR1201  0_0402_5%  [R_0402]  102.97 110.57 0 bottom
PR1202  100K_0402_1%  [R_0402]  103.88 109.66 180 bottom
PR1203  0_0603_5%  [R_0603]  96.61 110.27 180 bottom
PR1204  0_0402_5%  [R_0402]  102.97 111.49 0 bottom
PR1205  100K_0402_1%  [R_0402]  102.97 112.4 0 bottom
PR1206  100K_0402_1%  [R_0402]  103.88 115.19 180 bottom
PR1207  100K_0402_1%  [R_0402]  102.97 114.25 0 bottom
PR1208  4.7_1206_5%  [R_1206]  95.99 107.76 270 bottom
PU100  SY8286BRAC_QFN20_3X3  [SY8286BRAC_QFN20_3X3-S]  174.67 44.15 270 bottom
PU102  SY8286CRAC_QFN20_3X3  [SY8286CRAC_QFN20_3X3-S]  177.36 34.15 270 bottom
PU200  RT8207PGQW_WQFN20_3X3  [RT8207PGQW_WQFN20_3X3-S]  86.79 108.22 0 bottom
PU300  SY8286RAC_QFN20_3X3  [SY8286RAC_QFN20_3X3-S]  149.67 44.2 270 bottom
PU500  RT8061AZQW_WDFN10_3X3  [SY8033BDBC_DFN10_3X3-S]  161.39 35.95 270 bottom
PU602  ISL95859HRTZ-T_TQFN40_5X5  [ISL62883CHRTZ-T_TQFN40_5X5-S]  166.07 57.16 90 top
PU603  -  [AOZ5019QI_QFN23_5X3P5]  161.22 82.69 270 bottom
PU604  -  [AOZ5019QI_QFN23_5X3P5]  150.85 103.96 270 bottom
PU605  -  [AOZ5019QI_QFN23_5X3P5]  153.83 94.25 270 bottom
PU606  ISL95808HRZ-TS2378_DFN8_2X2  [ISL95808HRZ-TS2378_DFN8_2X2-S]  151.81 72.66 270 bottom
PU703  ISL88739HRZ-T_QFN32_4X4  [ISL95520HRZ-T_QFN32_4X4-S]  192.41 34.43 0 bottom
PU800  RT9059GSP_SO8  [RT904225GSP_SO8]  52.57 9.27 270 bottom
PU1200  -  [NB681GD-Z_QFN13_2X3]  99.28 112.4 270 bottom
Q1  -  [2N7002K_SOT23-3]  42.08 3.33 270 bottom
Q2  -  [DMN66D0LDW-7_SOT363-6]  150.77 6.58 270 top
Q3  -  [DDTA144VCA-7-F_SOT23-3]  153.82 12.11 180 top
Q4  -  [DDTA144VCA-7-F_SOT23-3]  159.46 7.55 180 top
Q5  -  [2N7002K_SOT23-3]  155.34 5.33 0 top
Q6  -  [LN2306LT1G_SOT23-3]  79.9 3.05 0 top
Q7  -  [DDTA144VCA-7-F_SOT23-3]  83.84 6.02 180 top
Q8  -  [LN2306LT1G_SOT23-3]  115.02 11.62 180 bottom
Q9  -  [LN2306LT1G_SOT23-3]  102.6 5.24 0 top
Q10  -  [DMN66D0LDW-7_SOT363-6]  106.4 7.9 180 top
Q11  -  [DMN66D0LDW-7_SOT363-6]  114.01 112.25 270 bottom
Q12  NTK3139PT1G_SOT723-3  [2N7002K_SOT23-3]  91.74 10.06 90 top
Q13  -  [2N7002K_SOT23-3]  90.02 5.99 90 top
Q14  -  [LMBT3904LT1G_SOT23-3]  62.78 96.54 270 bottom
Q15  -  [DDTA144VCA-7-F_SOT23-3]  175.91 19.35 180 top
Q16  -  [LN2306LT1G_SOT23-3]  171.41 14.53 180 top
QA1  -  [LN2306LT1G_SOT23-3]  40.48 12.63 0 top
QC1  -  [DMN66D0LDW-7_SOT363-6]  114.97 29.48 180 top
QC2  -  [2N7002K_SOT23-3]  88.41 23.54 180 top
QI1  -  [2N7002K_SOT23-3]  23.62 79.9 270 top
QI2  -  [DMN66D0LDW-7_SOT363-6]  30.31 71.82 90 top
QI3  2N7002W-7-F_1N_SOT323-3  [SSM3K7002FU_SC70-3]  32.16 71.14 0 top
R1  1K_0402_5%  [R_0402]  30.7 7.96 180 bottom
R2  10M_0402_5%  [R_0402]  37.93 4.14 90 top
R3  0_0805_5%  [R_0805]  222.97 28.05 270 bottom
R5  10K_0402_5%  [R_0402]  220.81 46.21 0 bottom
R6  0_0402_5%  [R_0402]  221.72 45.32 180 bottom
R8  0_0402_5%  [R0402_0OHM]  218.65 23.13 90 bottom
R9  0_0402_5%  [R_0402]  218.65 23.13 90 top
R10  100K_0402_5%  [R_0402]  223.41 23.89 90 bottom
R11  0_0603_5%  [R_0603]  227.41 34.88 0 top
R12  0_0603_5%  [R_0603]  228.36 29.81 180 top
R13  0_0603_5%  [R_0603]  225.95 29.81 180 top
R16  0_0603_5%  [R_0603]  226.25 36.29 270 top
R17  0_0402_5%  [R_0402-NPM]  221.2 35.58 180 bottom
R18  0_0402_5%  [R_0402-NPM]  221.2 34.69 180 bottom
R19  33_0402_5%  [R_0402]  221.06 30.9 270 top
R20  0_0402_5%  [R_0402]  220.68 26.64 270 bottom
R21  0_0402_5%  [R_0402]  221.57 26.64 270 bottom
R22  100_0402_5%  [R_0402]  154.76 106.58 0 top
R23  10K_0402_5%  [R_0402]  156.29 10.01 270 top
R24  100K_0402_5%  [R_0402]  80.68 6.82 180 top
R25  1K_0402_5%  [R_0402]  85.3 6.81 90 top
R26  51K_0402_5%  [R_0402]  118.38 11.77 270 bottom
R27  100K_0402_5%  [R_0402]  117.49 11.77 270 bottom
R28  18.7K_0402_1%  [R_0402]  118.37 109.83 270 bottom
R29  2K_0402_1%  [R_0402]  109.54 111.6 270 bottom
R30  10K_0402_5%  [R_0402]  183.48 52.35 225 top
R31  4.7K_0402_5%  [R_0402]  93.71 12.27 0 bottom
R32  4.7K_0402_5%  [R_0402]  93.71 11.38 0 bottom
R33  4.7K_0402_5%  [R_0402]  105.89 4.98 180 top
R34  4.7K_0402_5%  [R_0402]  106.88 8.91 0 top
R35  0_0402_5%  [R_0402]  86.95 9.37 270 top
R36  0_0603_5%  [R_0603]  93.17 7.58 270 top
R37  100_0603_1%  [R_0603]  91.97 6.18 90 top
R38  20K_0402_1%  [R_0402]  87.9 11.09 270 top
R39  10K_0402_5%  [R_0402]  100.03 8.22 270 top
R40  4.7K_0402_5%  [R_0402]  103.98 9.04 180 top
R41  100K_0402_5%  [R_0402]  100.03 9.21 90 top
R42  24.9K_0402_1%  [R_0402]  109.86 13.8 0 bottom
R43  10K_0402_1%  [R_0402]  109.86 14.69 0 bottom
R44  THINK_0603_1%_TSM1B104F3591RZ  [R_0603]  109.68 75.96 180 top
R45  0_0402_5%  [R_0402]  110.78 12.02 180 bottom
R46  2.2K_0402_5%  [R_0402]  107.67 4.97 180 top
R47  2.2K_0402_5%  [R_0402]  104.86 9.94 270 top
R48  2.2K_0402_5%  [R_0402]  114.97 111.46 90 bottom
R49  2.2K_0402_5%  [R_0402]  110.59 111.6 270 bottom
R50  10K_0402_5%  [R_0402]  182.78 52.99 225 top
R51  0_0805_5%  [R0805_0OHM]  223.98 48.45 90 top
R53  100K_0402_5%  [R_0402]  168.99 12.48 270 top
R54  0_0805_5%  [R_0805]  228.77 37.8 270 top
R55  0_0603_5%  [R0603_0OHM]  184.92 55.02 135 top
R56  0_0402_5%  [R_0402]  221.2 36.47 180 bottom
R57  10K_0402_5%  [R_0402]  228.11 25.72 90 bottom
RA1  0_0805_5%  [R0805_0OHM]  37.93 23.68 90 top
RA2  0_0402_5%  [R0402_0OHM]  25.36 25.54 90 top
RA3  100K_0402_5%  [R_0402]  22.43 24.52 90 top
RA4  0_0603_5%  [R0603_0OHM]  24.66 8.91 90 top
RA5  0_0402_5%  [R0402_0OHM]  36.28 16.34 0 top
RA6  0_0402_5%  [R0402_0OHM]  38.87 16.46 0 top
RA7  33_0402_5%  [R_0402]  28.02 28.28 270 top
RA8  100K_0402_5%  [R_0402]  33.88 24.6 180 top
RA9  0_0402_5%  [R_0402]  30.18 27.31 90 top
RA10  200K_0402_1%  [R_0402]  21.53 23.46 0 top
RA11  0_0402_5%  [R_0402]  20.08 24.52 90 top
RA12  0_0402_5%  [R_0402]  21.04 24.52 90 top
RA13  BLM15PD800SN1D_2P  [MURAT_BLM15PD600SN1D_2P]  32.36 4.53 180 top
RA14  BLM15PD800SN1D_2P  [MURAT_BLM15PD600SN1D_2P]  32.34 2.37 180 top
RA15  BLM15PD800SN1D_2P  [MURAT_BLM15PD600SN1D_2P]  32.36 8.28 180 top
RA16  BLM15PD800SN1D_2P  [MURAT_BLM15PD600SN1D_2P]  32.36 6.31 180 top
RA17  0_0402_5%  [R0402_0OHM]  23.39 25.43 270 top
RA18  0_0402_5%  [R0402_0OHM]  32.63 14.39 0 top
RA22  0_0805_5%  [R0805_0OHM]  8.47 8.76 90 top
RA23  1K_0402_5%  [R_0402]  19.13 25.43 270 top
RA24  10K_0402_5%  [R_0402]  18.18 24.52 90 top
RA25  2.2K_0402_5%  [R_0402]  22.75 15.98 270 bottom
RA26  2.2K_0402_5%  [R_0402]  22.75 16.84 90 bottom
RA27  10_0402_1%  [R_0402]  26.45 10.94 180 bottom
RA28  1K_0402_5%  [R_0402]  24.59 11.33 270 bottom
RA29  4.7K_0402_5%  [R_0402]  23.64 11.33 270 bottom
RA30  10K_0402_5%  [R_0402]  21.55 11.33 270 bottom
RA31  10_0402_1%  [R_0402]  26.45 13.23 180 bottom
RA32  1K_0402_5%  [R_0402]  24.59 12.77 90 bottom
RA33  4.7K_0402_5%  [R_0402]  23.64 12.77 90 bottom
RA34  10K_0402_5%  [R_0402]  21.55 12.77 90 bottom
RA35  BLM15PX330SN1D_2P  [MURAT_BLM15PX330SN1D_2P]  21.61 15.01 90 bottom
RA36  0_0402_5%  [R0402_0OHM]  22.63 10.42 90 bottom
RA37  0_0402_5%  [R0402_0OHM]  22.63 13.7 270 bottom
RA38  BLM15PX330SN1D_2P  [MURAT_BLM15PX330SN1D_2P]  21.67 17.67 270 bottom
RA39  0_0603_5%  [R0603_0OHM]  15.64 18.82 90 bottom
RA40  0_0402_5%  [R0402_0OHM]  15.77 22.07 270 bottom
RA41  100K_0402_5%  [R_0402]  25.7 12.99 90 top
RA42  33_0402_5%  [R_0402]  30.69 25.68 270 top
RC1  2.2K_0402_5%  [R_0402]  128.15 32.96 0 bottom
RC2  2.2K_0402_5%  [R_0402]  128.15 32.07 0 bottom
RC3  10K_0402_5%  [R_0402]  128.15 33.85 0 bottom
RC4  24.9_0402_1%  [R_0402]  120.35 62.21 90 top
RC5  10K_0402_5%  [R_0402]  117.75 35.88 90 top
RC6  100K_0402_5%  [R_0402]  115.59 24.39 90 bottom
RC7  100_0402_1%  [R_0402]  127.9 40.1 270 bottom
RC8  200_0402_1%  [R_0402]  106.05 30.42 0 bottom
RC9  100K_0402_5%  [R_0402]  92.54 84.96 270 top
RC10  121_0402_1%  [R_0402]  92.55 43.05 180 top
RC11  80.6_0402_1%  [R_0402]  92.54 44.84 180 top
RC12  100_0402_1%  [R_0402]  92.55 43.94 180 top
RC13  10K_0402_5%  [R_0402]  91.64 36.58 0 top
RC14  10K_0402_5%  [R_0402]  91.64 35.69 0 top
RC15  22_0402_5%  [R_0402]  97 33.1 180 bottom
RC16  22_0402_5%  [R_0402]  97 33.99 180 bottom
RC17  0_0603_5%  [R0603_0OHM]  88.47 26.8 180 top
RC18  4.7K_0402_5%  [R_0402]  105.05 29.28 90 bottom
RC19  1K_0402_5%  [R_0402]  106 28.1 270 bottom
RC20  1K_0402_5%  [R_0402]  96.35 29.26 90 bottom
RC21  33_0402_5%  [R_0402]  105.68 17.72 0 bottom
RC22  33_0402_5%  [R_0402]  104.16 30.18 270 bottom
RC23  33_0402_5%  [R_0402]  101.37 30.19 270 bottom
RC24  33_0402_5%  [R_0402]  98.25 30.19 270 bottom
RC25  33_0402_5%  [R_0402]  97.3 30.18 270 bottom
RC26  33_0402_5%  [R_0402]  102.26 30.18 270 bottom
RC27  2.2K_0402_5%  [R_0402]  112.67 26.42 90 top
RC28  2.2K_0402_5%  [R_0402]  116.03 28.14 90 top
RC29  1K_0402_5%  [R_0402]  114.51 27.58 270 bottom
RC30  1K_0402_5%  [R_0402]  115.4 27.58 270 bottom
RC31  1K_0402_5%  [R_0402]  116.86 29.88 270 bottom
RC32  1K_0402_5%  [R_0402]  117.81 29.87 270 bottom
RC33  1K_0402_5%  [R_0402]  113.71 29.87 270 bottom
RC34  1K_0402_5%  [R_0402]  114.59 29.87 270 bottom
RC35  8.2K_0402_5%  [R_0402]  96.1 35.76 90 bottom
RC36  8.2K_0402_5%  [R_0402]  97 34.88 180 bottom
RC37  8.2K_0402_5%  [R_0402]  113.62 26.66 90 bottom
RC38  10K_0402_5%  [R_0402]  115.46 29.86 270 bottom
RC39  150K_0402_5%  [R_0402]  110.07 27.83 270 top
RC40  1K_0402_1%  [R_0402]  100.48 29.28 90 bottom
RC41  1K_0402_1%  [R_0402]  103.14 29.26 90 bottom
RC42  10K_0402_5%  [R_0402]  111.46 30.1 90 bottom
RC43  49.9K_0402_1%  [R_0402]  111.02 27.83 270 top
RC44  4.7K_0402_5%  [R_0402]  96.08 31.39 0 bottom
RC45  10K_0402_5%  [R_0402]  88.23 27.95 180 top
RC46  10K_0402_5%  [R_0402]  118.33 27.89 180 bottom
RC47  10K_0402_5%  [R_0402]  110.57 30.19 270 bottom
RC51  10K_0402_5%  [R_0402]  98.45 15.05 90 bottom
RC52  10K_0402_5%  [R_0402]  97.57 16.46 180 bottom
RC53  10K_0402_5%  [R_0402]  85.55 32.06 90 top
RC54  10K_0402_5%  [R_0402]  86.44 32.98 270 top
RC55  10K_0402_5%  [R_0402]  112.73 26.66 90 bottom
RC56  10K_0402_5%  [R_0402]  112.8 30.32 270 bottom
RC57  10K_0402_5%  [R_0402]  85.55 30.56 270 top
RC58  10K_0402_5%  [R_0402]  86.44 29.65 90 top
RC59  10K_0402_5%  [R_0402]  84.6 30.67 90 top
RC60  10K_0402_5%  [R_0402]  87.32 33.99 0 top
RC61  10K_0402_5%  [R_0402]  88.41 29.71 90 top
RC62  10K_0402_5%  [R_0402]  88.41 31.49 90 top
RC63  10K_0402_5%  [R_0402]  117.42 27.01 0 bottom
RC64  10K_0402_5%  [R_0402]  117.42 26.12 0 bottom
RC65  100_0402_1%  [R_0402]  119.45 35.82 0 top
RC66  113_0402_1%  [R_0402]  113.48 37.35 0 top
RC67  1K_0402_5%  [R_0402]  109.68 30.19 270 bottom
RC68  1K_0402_5%  [R_0402]  108.8 30.19 270 bottom
RC69  10K_0402_5%  [R_0402]  117.89 24.08 180 bottom
RC70  10K_0402_5%  [R_0402]  117.89 24.97 180 bottom
RC72  10K_0402_5%  [R_0402]  99.33 15.05 90 bottom
RC73  10K_0402_5%  [R_0402]  87.32 28.84 0 top
RC74  0_0402_5%  [R_0402]  82.18 28.47 0 top
RC75  0_0402_5%  [R_0402]  82.18 27.58 0 top
RC76  2.71K_0402_1%  [R_0402]  125.87 55.05 45 bottom
RC77  20K_0402_5%  [R_0402]  91.65 26.5 270 top
RC78  20K_0402_5%  [R_0402]  89.86 25.6 0 top
RC80  1M_0402_1%  [R_0402]  130.26 53.46 90 bottom
RC81  0_0402_5%  [R_0402]  130.26 51.68 90 bottom
RC82  10M_0402_5%  [R_0402]  91.38 33.22 0 top
RC83  0_0402_5%  [R0402_0OHM]  89.6 33.22 0 top
RC84  10K_0402_5%  [R_0402]  92.55 27.63 180 top
RC85  10K_0402_5%  [R_0402]  106.7 22.8 90 bottom
RC86  10K_0402_5%  [R_0402]  123.4 29.28 90 bottom
RC87  100K_0402_5%  [R_0402]  97.19 43.5 180 bottom
RC88  10K_0402_5%  [R_0402]  36.4 3.12 90 top
RC89  8.2K_0402_5%  [R_0402]  90.2 36.67 180 top
RC90  10K_0402_5%  [R_0402]  90.39 37.66 180 top
RC91  330K_0402_5%  [R_0402]  85.17 27 270 top
RC92  10K_0402_5%  [R_0402]  108.85 31.77 0 top
RC93  100K_0402_5%  [R_0402]  89.29 35.78 0 top
RC94  10K_0402_5%  [R_0402]  82.61 29.9 90 top
RC95  1K_0402_5%  [R_0402]  125.82 78.24 180 bottom
RC96  60.4_0402_1%  [R_0402]  127.67 73.29 180 bottom
RC97  0_0402_5%  [R0402_0OHM]  98.51 43.19 90 bottom
RC99  0_0402_5%  [R0402_0OHM]  91.64 39.45 0 top
RC100  0_0402_5%  [R_0402]  108.22 23.06 90 bottom
RC102  1M_0402_5%  [R_0402]  83.66 17.62 180 top
RC103  10K_0402_1%  [R_0402]  85.86 17.69 90 top
RC104  1K_0402_5%  [R_0402]  131.78 73.75 270 top
RC105  10K_0402_5%  [R_0402]  124.28 29.29 0 bottom
RC106  0_0402_5%  [R0402_0OHM]  126.07 29.41 90 bottom
RC107  0_0402_5%  [R0402_0OHM]  125.19 30.18 180 bottom
RC108  0_0402_5%  [R_0402]  105.95 19.1 90 bottom
RC109  100K_0402_5%  [R_0402]  105.95 20.87 90 bottom
RC110  1K_0402_5%  [R_0402]  83.97 28.47 270 top
RC111  49.9_0402_1%  [R_0402]  127.48 68.02 180 bottom
RC112  1K_0402_5%  [R_0402]  128.34 68.02 0 bottom
RC113  1K_0402_5%  [R_0402]  129.44 72.33 180 bottom
RC114  10K_0402_5%  [R_0402]  95.27 16.39 90 bottom
RC115  10K_0402_5%  [R_0402]  130.26 33.78 90 bottom
RC117  499_0402_1%  [R_0402]  127.6 72.33 180 bottom
RC118  0_0402_5%  [R_0402]  129.06 34.75 180 bottom
RC119  49.9_0402_1%  [R_0402]  92.55 41.28 180 top
RC120  49.9_0402_1%  [R_0402]  92.55 42.17 180 top
RC121  49.9_0402_1%  [R_0402]  126.75 75.06 0 bottom
RC122  49.9_0402_1%  [R_0402]  126.75 74.18 0 bottom
RC123  33_0402_5%  [R_0402]  79.97 18.28 90 top
RC124  33_0402_5%  [R_0402]  81.17 22.16 90 top
RC125  33_0402_5%  [R_0402]  80.28 22.16 90 top
RC126  1K_0402_5%  [R_0402]  79.39 22.16 90 top
RC127  33_0402_5%  [R_0402]  80.92 18.28 90 top
RC128  8.2K_0402_5%  [R_0402]  107.01 26.11 45 bottom
RC129  4.7K_0402_5%  [R_0402]  86.13 27 270 top
RC130  200_0402_1%  [R_0402]  112.15 35.39 0 top
RC131  10K_0402_1%  [R_0402]  128.43 75.95 180 bottom
RC132  10K_0402_1%  [R_0402]  128.43 76.9 180 bottom
RC133  10K_0402_1%  [R_0402]  123.84 78.25 270 bottom
RC134  49.9_0402_1%  [R_0402]  128.34 67.06 0 bottom
RC136  10K_0402_1%  [R_0402]  120.35 74.92 90 top
RC137  0_0402_5%  [R_0402]  122.51 30.19 270 bottom
RC138  100K_0402_5%  [R_0402]  129.44 71.38 180 bottom
RC139  1K_0402_5%  [R_0402]  99.14 30.19 270 bottom
RC140  51_0402_5%  [R_0402]  128.34 66.11 0 bottom
RC141  51_0402_5%  [R_0402]  119.08 66.99 90 top
RC142  51_0402_5%  [R_0402]  128.16 64.22 270 bottom
RC143  1K_0402_5%  [R_0402]  129.32 30.47 180 bottom
RC144  0_0402_5%  [R_0402]  129.67 78.25 0 bottom
RC145  0_0402_5%  [R_0402]  106.77 24.97 135 bottom
RC146  51_0402_1%  [R_0402]  126.56 67.06 0 bottom
RC147  51_0402_5%  [R_0402]  129.05 64.22 270 bottom
RC148  1K_0402_5%  [R_0402]  81.68 30.82 270 top
RC149  0_0603_5%  [R_0603]  131.72 27.25 180 bottom
RC150  100_0402_1%  [R_0402]  131.78 55.49 90 top
RC151  100_0402_1%  [R_0402]  131.78 57.27 90 top
RC152  56_0402_1%  [R_0402]  129.38 69.79 180 bottom
RC153  220_0402_5%  [R_0402]  126.69 69.79 0 bottom
RC154  100_0402_1%  [R_0402]  127.6 71.38 180 bottom
RC155  100_0402_1%  [R_0402]  118.96 77.29 270 bottom
RC156  100_0402_1%  [R_0402]  118 76.38 90 bottom
RC157  100_0402_1%  [R_0402]  108.35 73.81 180 top
RC158  100_0402_1%  [R_0402]  105.35 74.82 0 top
RC159  100_0402_1%  [R_0402]  132.72 45.13 180 top
RC160  100_0402_1%  [R_0402]  131.82 45.99 0 top
RC161  0_0603_5%  [R0603_0OHM]  130.81 41.36 0 bottom
RC162  0_0603_5%  [R0603_0OHM]  130.83 42.62 0 bottom
RC163  0_0603_5%  [R0603_0OHM]  92.74 20.25 180 top
RC164  10K_0402_5%  [R_0402]  85.93 20.71 90 top
RC169  0_0603_5%  [R0603_0OHM]  131.32 32.81 270 bottom
RC170  0_0603_5%  [R0603_0OHM]  139.4 42.82 180 top
RC171  0_0603_5%  [R0603_0OHM]  134.83 49.29 0 top
RC173  0_0603_5%  [R0603_0OHM]  135.47 45.23 270 bottom
RC174  0_0603_5%  [R0603_0OHM]  130.3 28.52 0 bottom
RC175  0_0402_5%  [R_0402]  127.9 78.25 0 bottom
RC176  15_0402_1%  [R_0402]  119.39 18.32 270 bottom
RC177  15_0402_1%  [R_0402]  113.38 22.69 180 bottom
RC178  15_0402_1%  [R_0402]  108.81 18.17 180 bottom
RC179  15_0402_1%  [R_0402]  108.81 17.28 180 bottom
RC180  15_0402_1%  [R_0402]  118.14 21.54 180 bottom
RC181  10K_0402_5%  [R_0402]  120.73 29.29 90 bottom
RC182  10K_0402_5%  [R_0402]  121.62 30.2 270 bottom
RC187  10K_0402_5%  [R_0402]  97.73 38.56 0 bottom
RC188  10K_0402_5%  [R_0402]  90.49 34.75 0 top
RC189  0_0402_5%  [R_0402]  82.18 26.69 0 top
RC192  1M_0402_1%  [R_0402]  83.66 16.69 180 top
RD1  0_0402_5%  [R_0402]  60.53 18.87 90 top
RD2  0_0402_5%  [R_0402]  66.39 19.77 180 top
RD3  0_0402_5%  [R_0402]  58.63 41.6 90 top
RD4  0_0402_5%  [R0402_0OHM]  61.42 19.79 270 top
RD5  0_0402_5%  [R0402_0OHM]  64.6 19.79 270 top
RD6  0_0402_5%  [R0402_0OHM]  59.52 42.52 270 top
RD7  470_0402_1%  [R_0402]  58.69 63.47 270 top
RD8  0_0402_5%  [R0402_0OHM]  60.5 62.57 180 top
RD9  2_0402_1%  [R_0402]  57.73 43.39 0 top
RD10  1K_0402_1%~D  [R_0402]  58.63 46.07 270 top
RD11  24.9_0402_1%  [R_0402]  55.95 44.16 0 top
RD12  1K_0402_1%~D  [R_0402]  58.64 44.28 180 top
RD13  0_0402_5%  [R_0402]  51.2 20.61 270 top
RD14  0_0402_5%  [R0402_0OHM]  46.63 19.82 90 top
RD15  0_0402_5%  [R_0402]  44.46 43.33 0 top
RD16  0_0402_5%  [R0402_0OHM]  50.31 20.61 270 top
RD17  0_0402_5%  [R_0402]  47.52 20.74 270 top
RD18  0_0402_5%  [R0402_0OHM]  45.37 42.44 180 top
RD19  2_0402_1%  [R_0402]  44.46 46.06 0 top
RD20  1K_0402_1%~D  [R_0402]  44.46 46.95 0 top
RD21  1K_0402_1%~D  [R_0402]  45.37 45.17 180 top
RD22  24.9_0402_1%  [R_0402]  42.68 45.17 0 top
RD23  240_0402_1%  [R_0402]  58.62 53.87 0 top
RD24  240_0402_1%  [R_0402]  45.24 54.63 180 top
RE1  100K_0402_1%  [R_0402]  148.79 13.17 0 top
RE2  0_0603_5%  [R0603_0OHM]  141.18 19.26 180 top
RE3  100K_0402_1%  [R_0402]  150.97 21.49 180 top
RE4  100K_0402_1%  [R_0402]  150.97 20.6 180 top
RE6  100K_0402_1%  [R_0402]  148.79 14.06 0 top
RE7  0_0603_5%  [R0603_0OHM]  145.82 13.04 270 bottom
RE8  4.7K_0402_5%  [R_0402]  138.33 20.72 180 bottom
RE9  4.7K_0402_5%  [R_0402]  138.33 21.61 180 bottom
RE10  2.2K_0402_5%  [R_0402]  138.46 22.5 180 bottom
RE11  2.2K_0402_5%  [R_0402]  138.46 23.39 180 bottom
RE12  10K_0402_5%  [R_0402]  138.65 33.36 180 bottom
RE13  10K_0402_5%  [R_0402]  145.07 32.35 180 top
RE14  100K_0402_5%  [R_0402]  141.51 34.57 180 bottom
RE15  100K_0402_5%  [R_0402]  155.85 29.82 270 top
RE16  10K_0402_5%  [R_0402]  153.82 27.91 270 top
RE17  100K_0402_5%  [R_0402]  138.46 24.28 180 bottom
RE18  100K_0402_5%  [R_0402]  138.46 18.69 180 bottom
RE19  1K_0402_5%  [R_0402]  152.37 25.23 180 top
RE20  10K_0402_5%  [R_0402]  158 22.56 0 bottom
RE21  100K_0402_5%  [R_0402]  150.77 14.96 270 top
RE22  0_0402_5%  [R0402_0OHM]  157.89 20.78 180 top
RE23  43_0402_1%  [R_0402]  156.62 19.77 180 top
RE24  0_0402_5%  [R_0402]  153.5 14.17 90 bottom
RE25  100K_0402_5%  [R_0402]  144.29 35.85 270 top
RE26  0_0402_5%  [R_0402]  152.57 14.09 90 bottom
RE27  0_0402_5%  [R_0402]  151.58 29.77 90 top
RE28  0_0402_5%  [R0402_0OHM]  145.49 14.81 180 top
RE29  1K_0402_5%  [R_0402]  146.53 19.77 90 top
RE30  100K_0402_5%  [R_0402]  142.94 17.68 0 top
RE32  100K_0402_5%  [R_0402]  145.64 19.77 90 top
RE33  15_0402_1%  [R_0402]  137.55 31.2 0 bottom
RE34  15_0402_1%  [R_0402]  137.55 29.4 0 bottom
RE35  15_0402_1%  [R_0402]  137.55 30.29 0 bottom
RE37  0_0402_5%  [R0402_0OHM]  137.29 26.18 0 bottom
RE38  0_0402_5%  [R_0402]  138.47 28.51 180 bottom
RE40  10K_0402_5%  [R_0402]  145.62 17.69 270 top
RE41  100K_0402_5%  [R_0402]  139.46 15.02 270 bottom
RE42  0_0402_5%  [R0402_0OHM]  147.94 34.61 180 bottom
RE43  100_0402_5%  [R_0402]  139.47 13.24 270 bottom
RE44  0_0402_5%  [R_0402]  146.46 14.45 90 top
RE45  0_0402_5%  [R_0402]  142.53 14.95 180 bottom
RE46  10K_0402_1%  [R_0402]  143.13 28.62 180 top
RE47  0_0402_5%  [R_0402]  143.39 14.95 0 bottom
RE48  10K_0402_1%  [R_0402]  140.86 28.6 180 top
RE49  100K_0402_5%  [R_0402]  143.8 27.51 180 top
RE50  0_0603_5%  [R0603_0OHM]  148.58 16.88 0 top
RE51  300_0402_5%  [R_0402]  149.22 19.76 90 top
RE52  100K_0402_5%  [R_0402]  142.25 25.99 0 top
RE53  100K_0402_5%  [R_0402]  151.44 24.01 0 top
RE54  300_0402_5%  [R_0402]  147.43 19.76 90 top
RE55  10K_0402_5%  [R_0402]  131.15 11.72 270 top
RE56  10K_0402_5%  [R_0402]  133.81 11.72 270 top
RE57  100K_0402_5%  [R_0402]  132.04 11.72 270 top
RE58  49.9_0402_1%  [R_0402]  126.7 11.72 270 top
RE59  10K_0402_5%  [R_0402]  132.92 11.72 270 top
RE60  0_0402_5%  [R0402_0OHM]  127.59 11.72 270 top
RE61  0_0402_5%  [R0402_0OHM]  128.48 11.72 270 top
RE63  0_0402_5%  [R0402_0OHM]  130.26 11.72 270 top
RE64  0_0402_5%  [R0402_0OHM]  146.78 13 180 top
RI1  5.6_0402_1%  [R_0402]  19.4 88.23 180 top
RI2  5.6_0402_1%  [R_0402]  19.4 87.34 180 top
RI3  150_0402_5%  [R_0402]  17.04 87.32 90 top
RI4  5.6_0402_1%  [R_0402]  19.4 89.24 180 top
RI5  5.6_0402_1%  [R_0402]  19.4 90.13 180 top
RI6  150_0402_5%  [R_0402]  17.04 89.29 90 top
RI7  5.6_0402_1%  [R_0402]  19.4 86.26 180 top
RI8  5.6_0402_1%  [R_0402]  19.4 85.37 180 top
RI9  150_0402_5%  [R_0402]  17.04 85.36 90 top
RI10  5.6_0402_1%  [R_0402]  19.4 84.35 180 top
RI11  5.6_0402_1%  [R_0402]  19.4 83.46 180 top
RI12  150_0402_5%  [R_0402]  17.04 83.45 90 top
RI13  2.2K_0402_5%  [R_0402]  28.79 74.17 90 top
RI14  2.2K_0402_5%  [R_0402]  29.81 74.17 90 top
RI15  1M_0402_5%  [R_0402]  32.68 74.38 180 top
RI16  20K_0402_5%  [R_0402]  33.1 70.78 0 top
RL1  10K_0402_5%  [R_0402]  35.06 123.08 0 bottom
RL2  2.49K_0402_1%~D  [R_0402]  39.27 115.72 180 bottom
RL3  1K_0402_5%  [R_0402]  34.94 121.7 270 bottom
RL4  15K_0402_1%  [R_0402]  35.96 120.79 90 bottom
RL5  0_0603_5%  [R0603_0OHM]  38.63 114.7 90 top
RL6  100K_0402_5%  [R_0402]  25.55 122.57 90 bottom
RL7  10K_0402_5%  [R_0402]  25.55 121.7 270 bottom
RL12  0_0402_5%  [R0402_0OHM]  54.88 108.72 90 top
RL13  0_0402_5%  [R0402_0OHM]  29.92 115.97 0 bottom
RL14  75_0603_5%  [R_0603]  20.28 112.03 180 top
RL15  75_0603_5%  [R_0603]  20.28 108.48 180 top
RL16  10K_0402_5%  [R_0402]  28.14 115.97 0 bottom
RP1  100K_8P4R_5%  [RP_0804_8P4R]  222.65 42.41 0 top
RP2  100_8P4R_5%  [RP_0804_8P4R]  223.78 43.9 180 top
RPC1  10K_8P4R_5%  [RP_0804_8P4R]  130.76 35.96 0 bottom
RPE1  10K_8P4R_5%  [RP_0804_8P4R]  143.04 21.87 0 top
RPE2  10K_8P4R_5%  [RP_0804_8P4R]  147.67 14.34 270 bottom
RPE3  100K_8P4R_5%  [RP_0804_8P4R]  144.1 23.32 180 top
RPE4  100K_8P4R_5%  [RP_0804_8P4R]  143.35 36.16 270 bottom
RPE5  100K_8P4R_5%  [RP_0804_8P4R]  159.66 28.39 180 bottom
RPE6  100K_8P4R_5%  [RP_0804_8P4R]  159.6 20.84 180 bottom
RPI1  470_8P4R_5%  [RP_0804_8P4R]  20.16 79.71 90 top
RPI2  470_8P4R_5%  [RP_0804_8P4R]  17.18 79.71 90 top
RS1  0_0402_5%  [R_0402]  187.24 24.97 90 bottom
RU1  0_0402_5%  [R_0402-NPM]  24.2 57.87 0 top
RU2  0_0402_5%  [R_0402-NPM]  24.2 56.98 0 top
RU3  0_0402_5%  [R_0402]  19.82 61.62 0 top
RU4  0_0402_5%  [R_0402]  19.82 62.51 0 top
RU5  0_0402_5%  [R_0402]  19.82 59.84 0 top
RU6  0_0402_5%  [R_0402]  19.82 60.73 0 top
RU7  0_0402_5%  [R_0402-NPM]  26 35.2 180 top
RU8  0_0402_5%  [R_0402-NPM]  26 36.09 180 top
RU9  0_0402_5%  [R_0402]  19.88 39.97 0 top
RU10  0_0402_5%  [R_0402]  19.88 40.85 0 top
RU11  0_0402_5%  [R_0402]  19.88 38.19 0 top
RU12  0_0402_5%  [R_0402]  19.88 39.08 0 top
RU13  0_0402_5%  [R_0402-NPM]  179.6 23.46 270 bottom
RU14  0_0402_5%  [R_0402-NPM]  178.71 23.46 270 bottom
RU15  0_0402_5%  [R_0402-NPM]  183.54 23.21 270 bottom
RU16  0_0402_5%  [R_0402-NPM]  182.65 23.21 270 bottom
